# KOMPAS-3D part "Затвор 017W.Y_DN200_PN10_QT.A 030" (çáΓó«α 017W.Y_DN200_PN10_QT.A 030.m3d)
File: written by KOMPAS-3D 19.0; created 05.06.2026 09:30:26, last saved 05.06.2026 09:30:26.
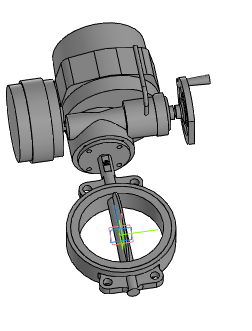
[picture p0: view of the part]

Document properties: Автор: Энергия; Полное имя файла: ..\..\..\3d для проектировщиков\x.x Тип 017W.Y(S) Затвор дисковый поворотный межфланцевый\Затвор 017W.Y(S)_DN32-DN1200_QT.A_MT903.A\Затвор 017W.Y_DN200_PN10_QT.A 030.a3d

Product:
- Part/product: Затвор 017W.Y_DN200_PN10_QT.A 030
    Масса: 127.269

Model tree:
1. Операция без истории:1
